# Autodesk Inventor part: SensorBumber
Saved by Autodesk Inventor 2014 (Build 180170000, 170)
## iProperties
Created: 2015-06
Part Number: SensorBumber
Material: Generic
Document SubType Name: Modeling
Designer: common
Density: 1 g/cm^3
Appearance: Default
Author: common
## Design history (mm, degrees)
node "SensorBumber.ipt1"
body "Solid2"
node "Base1"
